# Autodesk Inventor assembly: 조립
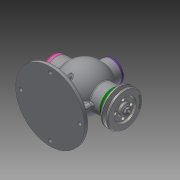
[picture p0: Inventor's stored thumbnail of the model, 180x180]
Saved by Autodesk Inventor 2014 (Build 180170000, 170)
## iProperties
Created: 2020-08
Part Number: 조립
Document SubType Name: Assembly
Designer: kh
Author: kh
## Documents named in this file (18)
- C:\Users\kh\Desktop\700806V1028\조립.iam
- C:\Users\kh\Desktop\700806V1028\본체.ipt
- C:\Users\kh\Desktop\700806V1028\V-벨트풀리.ipt
- C:\Users\kh\Desktop\700806V1028\너트 M8.ipt
- C:\Users\kh\Desktop\700806V1028\뒤커버.ipt
- C:\Users\kh\Desktop\700806V1028\멈춤링 15x1.ipt
- C:\Users\kh\Desktop\700806V1028\멈춤링 35x1.6.ipt
- 멈춤링 35x1.6.ipt
- C:\Users\kh\Desktop\700806V1028\베어링 6202.ipt
- 베어링 6202.ipt
- C:\Users\kh\Desktop\700806V1028\볼트 M4.ipt
- C:\Users\kh\Desktop\700806V1028\상부커버.ipt
- C:\Users\kh\Desktop\700806V1028\슬라이드.ipt
- C:\Users\kh\Desktop\700806V1028\앞커버.ipt
- C:\Users\kh\Desktop\700806V1028\오일 실 15 30 7.ipt
- C:\Users\kh\Desktop\700806V1028\칼라.ipt
- C:\Users\kh\Desktop\700806V1028\키 3x3x12.ipt
- C:\Users\kh\Desktop\700806V1028\편심축.ipt
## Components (1 placed, 1 different names)
1. V-벨트풀리:1 — Insert:17, Mate:5, Insert:18
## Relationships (3: Insert 2, Mate 1)
- Insert:17: V-벨트풀리:1
- Mate:5: V-벨트풀리:1
- Insert:18: V-벨트풀리:1
